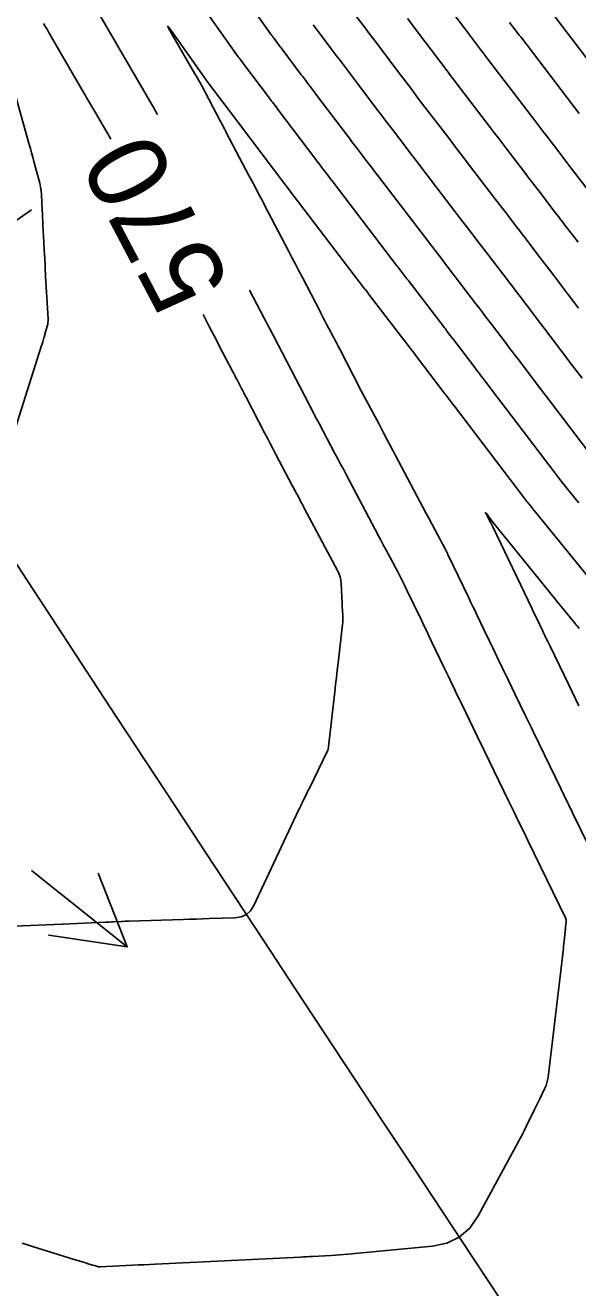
# Model space of a CAD drawing. Extents: x 954385 to 988206, y 1868364 to 1924553.
# Drawn here: x 957406.6 to 957448.5, y 1920437.4 to 1920532.9 of the extents above; entities that cross this region are included whole.
import ezdxf

# ---------------------------------------------------------------- set-up
doc = ezdxf.new("R2010")
doc.units = 0
for name, color, linetype in [('Default', 7, 'Continuous'), ('Ex_Contour Labels', 7, 'Continuous'), ('Ex_Major Contours', 7, 'Continuous'), ('Ex_Minor Contours', 7, 'Continuous'), ('Slopes', 7, 'Continuous')]:
    doc.layers.add(name, color=color, linetype=linetype)

msp = doc.modelspace()

# ---------------------------------------------------------------- linework, layer by layer
at = {"layer": 'Default'}
msp.add_arc((966995.782, 1926764.927), 11459.156, 211.4606918, 214.0750737, dxfattribs=at)
at = {"layer": 'Ex_Major Contours'}
for points in [[(957449.114, 1920500.826), (957446.06, 1920504.842), (957445.548, 1920505.515), (957445.037, 1920506.188), (957443.943, 1920507.626), (957443.722, 1920507.916), (957443.501, 1920508.207), (957443.281, 1920508.497), (957443.06, 1920508.787), (957441.933, 1920510.271), (957441.835, 1920510.4), (957441.737, 1920510.529), (957441.639, 1920510.658), (957441.541, 1920510.787), (957441.149, 1920511.303), (957441.051, 1920511.432), (957440.952, 1920511.561), (957440.854, 1920511.69), (957440.756, 1920511.818), (957438.698, 1920514.502), (957438.572, 1920514.667), (957438.445, 1920514.831), (957438.319, 1920514.996), (957438.193, 1920515.16), (957437.689, 1920515.818), (957437.562, 1920515.982), (957437.436, 1920516.147), (957437.31, 1920516.311), (957437.185, 1920516.476), (957433.308, 1920521.55), (957433.114, 1920521.803), (957432.92, 1920522.057), (957432.726, 1920522.311), (957432.532, 1920522.565), (957431.757, 1920523.58), (957431.563, 1920523.833), (957431.369, 1920524.087), (957431.176, 1920524.342), (957430.984, 1920524.596), (957428.799, 1920527.486), (957428.589, 1920527.763), (957428.38, 1920528.04), (957427.96, 1920528.595), (957427.856, 1920528.734), (957427.751, 1920528.872), (957427.646, 1920529.011), (957427.541, 1920529.15), (957426.004, 1920531.186), (957425.939, 1920531.273), (957425.873, 1920531.36), (957425.807, 1920531.447), (957425.741, 1920531.534), (957425.477, 1920531.883), (957425.411, 1920531.971), (957425.347, 1920532.059), (957425.282, 1920532.147), (957425.219, 1920532.236), (957421.065, 1920538.117)], [(957408.031, 1920533.031), (957408.178, 1920532.786), (957408.323, 1920532.541), (957408.467, 1920532.294), (957410.934, 1920528.044), (957411.16, 1920527.654), (957411.386, 1920527.264), (957411.613, 1920526.875), (957411.839, 1920526.485), (957412.987, 1920524.509), (957413.091, 1920524.327), (957413.119, 1920524.279)], [(957443.304, 1920533.114), (957443.722, 1920532.561), (957443.827, 1920532.422), (957443.932, 1920532.284), (957444.037, 1920532.146), (957444.142, 1920532.009), (957448.568, 1920526.218)], [(957420.103, 1920511.005), (957420.553, 1920510.142), (957420.749, 1920509.766), (957420.944, 1920509.391), (957421.14, 1920509.015), (957421.335, 1920508.64), (957422.338, 1920506.716), (957422.423, 1920506.552), (957422.509, 1920506.388), (957422.594, 1920506.224), (957422.68, 1920506.059), (957423.021, 1920505.403), (957423.107, 1920505.238), (957423.192, 1920505.074), (957423.278, 1920504.91), (957423.363, 1920504.745), (957424.755, 1920502.064), (957424.97, 1920501.653), (957425.185, 1920501.241), (957425.4, 1920500.831), (957425.617, 1920500.421), (957426.859, 1920498.075), (957426.95, 1920497.904), (957427.101, 1920497.618), (957427.162, 1920497.504), (957427.222, 1920497.39), (957427.507, 1920496.851), (957427.565, 1920496.742), (957427.623, 1920496.634), (957427.68, 1920496.525), (957427.738, 1920496.416), (957430.299, 1920491.587), (957430.398, 1920491.373), (957430.473, 1920491.152), (957430.522, 1920490.925), (957430.548, 1920490.691), (957430.606, 1920489.61), (957430.615, 1920489.437), (957430.624, 1920489.265), (957430.634, 1920489.093), (957430.643, 1920488.92), (957430.681, 1920488.231), (957430.687, 1920488.058), (957430.685, 1920487.886), (957430.676, 1920487.714), (957430.66, 1920487.543), (957430.32, 1920484.633), (957430.257, 1920484.09), (957430.194, 1920483.548), (957430.131, 1920483.006), (957430.068, 1920482.464), (957429.563, 1920478.105), (957429.558, 1920478.067), (957429.558, 1920478.062), (957429.556, 1920478.057), (957429.555, 1920478.053), (957429.553, 1920478.049), (957428.149, 1920475.175), (957428.083, 1920475.04), (957428.017, 1920474.906), (957427.951, 1920474.771), (957427.885, 1920474.636), (957427.622, 1920474.097), (957427.557, 1920473.962), (957427.492, 1920473.827), (957427.427, 1920473.692), (957427.363, 1920473.557), (957423.941, 1920466.29), (957423.696, 1920465.898), (957423.38, 1920465.613), (957422.993, 1920465.436), (957422.536, 1920465.365), (957420.565, 1920465.3), (957420.072, 1920465.283), (957419.58, 1920465.267), (957419.087, 1920465.251), (957418.594, 1920465.235), (957414.505, 1920465.102), (957414.355, 1920465.097), (957414.205, 1920465.092), (957414.055, 1920465.086), (957413.906, 1920465.079), (957413.307, 1920465.051), (957413.157, 1920465.044), (957413.007, 1920465.037), (957412.858, 1920465.031), (957412.708, 1920465.024), (957409.5, 1920464.876), (957409.439, 1920464.873), (957395.66, 1920464.306)]]:
    msp.add_lwpolyline(points, dxfattribs=at)
at = {"layer": 'Ex_Minor Contours'}
for points in [[(957448.551, 1920496.747), (957448.4, 1920496.933), (957448.249, 1920497.12), (957448.098, 1920497.306), (957447.947, 1920497.492), (957447.342, 1920498.237), (957447.192, 1920498.424), (957447.043, 1920498.612), (957446.896, 1920498.801), (957446.75, 1920498.992), (957442.633, 1920504.404), (957442.141, 1920505.052), (957441.32, 1920506.131), (957441.156, 1920506.347), (957440.992, 1920506.563), (957440.828, 1920506.779), (957440.663, 1920506.994), (957439.058, 1920509.107), (957438.935, 1920509.269), (957438.812, 1920509.432), (957438.566, 1920509.756), (957438.504, 1920509.837), (957438.442, 1920509.918), (957438.38, 1920509.999), (957438.318, 1920510.08), (957435.691, 1920513.506), (957435.615, 1920513.606), (957435.538, 1920513.706), (957435.462, 1920513.806), (957435.385, 1920513.906), (957435.078, 1920514.305), (957435.002, 1920514.405), (957434.925, 1920514.505), (957434.849, 1920514.605), (957434.772, 1920514.705), (957429.953, 1920521.012), (957429.843, 1920521.156), (957429.734, 1920521.3), (957429.624, 1920521.443), (957429.514, 1920521.587), (957429.076, 1920522.161), (957428.966, 1920522.304), (957428.857, 1920522.448), (957428.747, 1920522.592), (957428.638, 1920522.736), (957425.801, 1920526.489), (957425.632, 1920526.712), (957425.35, 1920527.085), (957425.294, 1920527.16), (957425.237, 1920527.234), (957425.181, 1920527.309), (957425.125, 1920527.383), (957423.172, 1920529.969), (957423.104, 1920530.06), (957423.036, 1920530.15), (957422.9, 1920530.33), (957422.866, 1920530.375), (957422.832, 1920530.421), (957422.799, 1920530.467), (957422.766, 1920530.513), (957417.792, 1920537.556)], [(957438.02, 1920535.141), (957439.887, 1920532.67), (957440.041, 1920532.467), (957440.194, 1920532.265), (957440.347, 1920532.062), (957440.5, 1920531.86), (957441.112, 1920531.05), (957441.266, 1920530.847), (957441.419, 1920530.645), (957441.573, 1920530.443), (957441.727, 1920530.241), (957445.212, 1920525.682), (957445.439, 1920525.385), (957445.666, 1920525.088), (957445.893, 1920524.791), (957446.12, 1920524.494), (957447.027, 1920523.307), (957447.254, 1920523.01), (957447.481, 1920522.713), (957447.708, 1920522.417), (957447.936, 1920522.12), (957449.844, 1920519.632)], [(957416.651, 1920526.138), (957416.609, 1920526.218), (957416.548, 1920526.329), (957416.486, 1920526.439), (957416.423, 1920526.549), (957412.117, 1920533.963)], [(957448.521, 1920511.494), (957448.373, 1920511.689), (957448.226, 1920511.883), (957447.635, 1920512.66), (957447.488, 1920512.854), (957447.34, 1920513.049), (957447.192, 1920513.243), (957447.045, 1920513.437), (957446.315, 1920514.397), (957446.144, 1920514.622), (957445.973, 1920514.847), (957445.801, 1920515.071), (957445.63, 1920515.295), (957444.688, 1920516.523), (957444.474, 1920516.803), (957444.26, 1920517.082), (957444.045, 1920517.361), (957443.831, 1920517.641), (957442.909, 1920518.843), (957442.684, 1920519.136), (957442.459, 1920519.43), (957442.234, 1920519.724), (957442.009, 1920520.018), (957440.018, 1920522.624), (957439.655, 1920523.098), (957439.293, 1920523.573), (957438.931, 1920524.047), (957438.568, 1920524.521), (957436.898, 1920526.706), (957436.646, 1920527.036), (957436.395, 1920527.366), (957436.144, 1920527.697), (957435.893, 1920528.028), (957434.795, 1920529.48), (957434.593, 1920529.747), (957434.391, 1920530.014), (957434.19, 1920530.281), (957433.988, 1920530.548), (957433.12, 1920531.696), (957432.949, 1920531.922), (957432.778, 1920532.149), (957432.607, 1920532.375), (957432.436, 1920532.602), (957431.669, 1920533.618)], [(957448.483, 1920516.49), (957448.319, 1920516.705), (957448.154, 1920516.919), (957447.496, 1920517.778), (957447.331, 1920517.993), (957447.167, 1920518.207), (957447.002, 1920518.422), (957446.838, 1920518.636), (957445.519, 1920520.355), (957445.244, 1920520.714), (957444.97, 1920521.072), (957444.696, 1920521.43), (957444.422, 1920521.789), (957443.102, 1920523.516), (957442.791, 1920523.923), (957442.48, 1920524.33), (957442.168, 1920524.738), (957441.857, 1920525.145), (957439.312, 1920528.474), (957439.109, 1920528.74), (957438.907, 1920529.006), (957438.705, 1920529.272), (957438.503, 1920529.539), (957437.696, 1920530.606), (957437.494, 1920530.873), (957437.293, 1920531.139), (957437.091, 1920531.406), (957436.889, 1920531.673), (957435.57, 1920533.418)], [(957459.028, 1920517.455), (957458.558, 1920518.072), (957458.543, 1920518.092), (957456.046, 1920521.378), (957456.014, 1920521.419), (957455.983, 1920521.46), (957455.873, 1920521.604), (957455.857, 1920521.624), (957452.619, 1920525.845), (957452.561, 1920525.92), (957452.503, 1920525.996), (957452.445, 1920526.072), (957452.387, 1920526.148), (957452.097, 1920526.528), (957451.981, 1920526.679), (957451.923, 1920526.755), (957446.556, 1920533.776)], [(957449.248, 1920491.148), (957445.296, 1920496.022), (957445.143, 1920496.21), (957444.99, 1920496.399), (957444.685, 1920496.775), (957444.609, 1920496.87), (957444.533, 1920496.965), (957444.459, 1920497.061), (957444.385, 1920497.157), (957439.206, 1920503.966), (957438.916, 1920504.347), (957438.627, 1920504.728), (957438.554, 1920504.823), (957438.482, 1920504.919), (957438.409, 1920505.014), (957438.337, 1920505.109), (957436.184, 1920507.943), (957436.083, 1920508.076), (957435.983, 1920508.209), (957435.957, 1920508.242), (957435.932, 1920508.275), (957435.907, 1920508.308), (957435.881, 1920508.341), (957432.685, 1920512.51), (957432.577, 1920512.651), (957432.468, 1920512.793), (957432.414, 1920512.864), (957432.36, 1920512.934), (957426.598, 1920520.475), (957426.496, 1920520.608), (957426.395, 1920520.742), (957426.369, 1920520.775), (957426.344, 1920520.808), (957426.319, 1920520.842), (957426.293, 1920520.875), (957422.795, 1920525.502), (957422.708, 1920525.617), (957420.34, 1920528.753), (957420.32, 1920528.78), (957420.313, 1920528.789), (957417.81, 1920532.334), (957417.537, 1920532.708), (957417.431, 1920532.822), (957417.491, 1920532.678), (957417.717, 1920532.275), (957419.49, 1920529.22), (957419.572, 1920529.078), (957419.654, 1920528.937), (957419.819, 1920528.654), (957419.86, 1920528.583), (957419.9, 1920528.511), (957419.939, 1920528.439), (957419.978, 1920528.367), (957421.405, 1920525.661), (957421.442, 1920525.592), (957421.478, 1920525.523), (957421.514, 1920525.454), (957421.55, 1920525.386), (957421.695, 1920525.11), (957421.731, 1920525.041), (957421.768, 1920524.973), (957421.804, 1920524.904), (957421.84, 1920524.835), (957423.605, 1920521.487), (957423.702, 1920521.303), (957423.799, 1920521.12), (957423.896, 1920520.937), (957423.993, 1920520.753), (957424.38, 1920520.02), (957424.477, 1920519.836), (957424.573, 1920519.653), (957424.67, 1920519.469), (957424.766, 1920519.285), (957426.567, 1920515.827), (957426.831, 1920515.321), (957427.095, 1920514.815), (957427.358, 1920514.308), (957427.622, 1920513.802), (957428.956, 1920511.242), (957429.08, 1920511.004), (957429.204, 1920510.765), (957429.329, 1920510.526), (957429.453, 1920510.287), (957429.95, 1920509.333), (957430.074, 1920509.094), (957430.198, 1920508.855), (957430.322, 1920508.616), (957430.446, 1920508.377), (957431.485, 1920506.378), (957431.681, 1920506), (957431.879, 1920505.622), (957432.077, 1920505.245), (957432.276, 1920504.868), (957433.424, 1920502.7), (957433.758, 1920502.068), (957433.854, 1920501.887), (957433.949, 1920501.707), (957434.345, 1920500.96), (957434.426, 1920500.806), (957434.508, 1920500.651), (957434.59, 1920500.497), (957434.672, 1920500.343), (957436.977, 1920495.995), (957437.211, 1920495.554), (957437.445, 1920495.113), (957438.047, 1920493.977), (957438.097, 1920493.883), (957438.147, 1920493.789), (957438.197, 1920493.695), (957438.247, 1920493.601), (957438.446, 1920493.224), (957438.496, 1920493.13), (957438.544, 1920493.035), (957438.592, 1920492.94), (957438.638, 1920492.844), (957440.192, 1920489.609), (957440.357, 1920489.265), (957440.523, 1920488.921), (957440.688, 1920488.577), (957440.853, 1920488.233), (957441.661, 1920486.55), (957441.753, 1920486.359), (957441.845, 1920486.169), (957441.936, 1920485.978), (957442.028, 1920485.787), (957442.496, 1920484.811), (957442.577, 1920484.641), (957442.659, 1920484.471), (957442.821, 1920484.131), (957442.862, 1920484.046), (957442.903, 1920483.961), (957442.944, 1920483.876), (957442.985, 1920483.792), (957443.709, 1920482.299), (957444.512, 1920480.643), (957444.661, 1920480.336), (957444.81, 1920480.03), (957444.959, 1920479.723), (957445.108, 1920479.416), (957446.782, 1920475.964), (957447.181, 1920475.142), (957447.238, 1920475.024), (957447.295, 1920474.907), (957447.352, 1920474.79), (957447.409, 1920474.672), (957447.792, 1920473.885), (957447.874, 1920473.714), (957447.957, 1920473.544), (957448.04, 1920473.374), (957448.123, 1920473.203), (957451.387, 1920466.489)], [(957448.792, 1920506.194), (957448.444, 1920506.651), (957448.097, 1920507.108), (957446.38, 1920509.366), (957446.195, 1920509.608), (957446.011, 1920509.85), (957445.827, 1920510.093), (957445.643, 1920510.335), (957444.807, 1920511.435), (957444.673, 1920511.612), (957444.538, 1920511.789), (957444.404, 1920511.966), (957444.27, 1920512.143), (957443.732, 1920512.85), (957443.597, 1920513.027), (957443.463, 1920513.204), (957443.328, 1920513.38), (957443.193, 1920513.557), (957441.704, 1920515.499), (957441.528, 1920515.728), (957441.353, 1920515.957), (957441.177, 1920516.186), (957441.001, 1920516.415), (957440.299, 1920517.33), (957440.123, 1920517.559), (957439.948, 1920517.789), (957439.772, 1920518.018), (957439.597, 1920518.247), (957436.663, 1920522.087), (957436.385, 1920522.451), (957436.107, 1920522.815), (957435.828, 1920523.179), (957435.55, 1920523.543), (957434.438, 1920524.998), (957434.16, 1920525.363), (957433.882, 1920525.727), (957433.605, 1920526.092), (957433.329, 1920526.457), (957431.797, 1920528.483), (957431.644, 1920528.686), (957431.49, 1920528.889), (957431.337, 1920529.091), (957431.184, 1920529.294), (957430.571, 1920530.105), (957430.418, 1920530.308), (957430.264, 1920530.51), (957430.111, 1920530.713), (957429.958, 1920530.916), (957428.837, 1920532.402), (957428.739, 1920532.531), (957428.641, 1920532.66), (957428.543, 1920532.79), (957428.446, 1920532.919)], [(957404.232, 1920497.233), (957407.888, 1920508.652), (957407.911, 1920508.724), (957407.933, 1920508.796), (957407.954, 1920508.869), (957407.975, 1920508.941), (957408.058, 1920509.232), (957408.079, 1920509.305), (957408.099, 1920509.378), (957408.12, 1920509.451), (957408.141, 1920509.523), (957408.315, 1920510.136), (957408.346, 1920510.263), (957408.366, 1920510.392), (957408.375, 1920510.521), (957408.373, 1920510.652), (957408.19, 1920513.916), (957408.178, 1920514.129), (957408.166, 1920514.342), (957408.155, 1920514.555), (957408.143, 1920514.768), (957408.095, 1920515.62), (957408.084, 1920515.833), (957408.072, 1920516.045), (957408.061, 1920516.258), (957408.05, 1920516.471), (957407.986, 1920517.767), (957407.971, 1920518.054), (957407.957, 1920518.341), (957407.943, 1920518.628), (957407.928, 1920518.915), (957407.87, 1920520.078), (957407.848, 1920520.367), (957407.809, 1920520.652), (957407.755, 1920520.936), (957407.686, 1920521.216), (957407.303, 1920522.593), (957407.213, 1920522.915), (957407.123, 1920523.237), (957407.034, 1920523.56), (957406.944, 1920523.882), (957405.362, 1920529.573)], [(957406.402, 1920440.741), (957406.805, 1920440.616), (957407.208, 1920440.49), (957410.348, 1920439.513), (957410.436, 1920439.486), (957410.525, 1920439.458), (957410.613, 1920439.43), (957410.702, 1920439.402), (957411.297, 1920439.214), (957411.319, 1920439.208), (957411.341, 1920439.201), (957411.749, 1920439.081), (957411.888, 1920439.04), (957412.12, 1920438.972), (957412.166, 1920438.96), (957412.213, 1920438.952), (957412.261, 1920438.949), (957412.309, 1920438.949), (957414.771, 1920439.07), (957415.198, 1920439.09), (957415.624, 1920439.111), (957416.05, 1920439.132), (957416.477, 1920439.153), (957427.483, 1920439.69), (957427.706, 1920439.701), (957427.929, 1920439.712), (957428.152, 1920439.723), (957428.375, 1920439.734), (957429.812, 1920439.806), (957430.125, 1920439.823), (957430.439, 1920439.844), (957430.752, 1920439.869), (957431.065, 1920439.897), (957437.46, 1920440.509), (957438.553, 1920440.736), (957439.495, 1920441.194), (957440.284, 1920441.881), (957440.921, 1920442.798), (957443.986, 1920448.441), (957444.134, 1920448.718), (957444.279, 1920448.996), (957444.421, 1920449.277), (957444.56, 1920449.559), (957445.19, 1920450.853), (957445.287, 1920451.054), (957445.385, 1920451.255), (957445.483, 1920451.455), (957445.58, 1920451.656), (957445.971, 1920452.458), (957446.06, 1920452.661), (957446.131, 1920452.869), (957446.184, 1920453.083), (957446.219, 1920453.302), (957447.353, 1920462.822), (957447.363, 1920462.913), (957447.374, 1920463.004), (957447.383, 1920463.095), (957447.393, 1920463.186), (957447.455, 1920463.806), (957447.46, 1920463.854), (957447.511, 1920464.334), (957447.519, 1920464.418), (957447.528, 1920464.502), (957447.537, 1920464.585), (957447.546, 1920464.669), (957447.583, 1920465.026), (957447.587, 1920465.112), (957447.578, 1920465.197), (957447.558, 1920465.279), (957447.525, 1920465.359), (957444.686, 1920471.203), (957444.321, 1920471.955), (957443.956, 1920472.707), (957443.591, 1920473.459), (957443.226, 1920474.212), (957441.405, 1920477.964), (957440.852, 1920479.104), (957439.678, 1920481.524), (957439.62, 1920481.644), (957439.562, 1920481.764), (957439.504, 1920481.884), (957439.446, 1920482.004), (957439.215, 1920482.485), (957439.1, 1920482.726), (957438.985, 1920482.966), (957438.651, 1920483.66), (957438.577, 1920483.816), (957438.502, 1920483.972), (957438.427, 1920484.127), (957438.352, 1920484.283), (957437.378, 1920486.31), (957437.191, 1920486.7), (957437.004, 1920487.09), (957436.816, 1920487.479), (957436.629, 1920487.869), (957435.538, 1920490.141), (957435.368, 1920490.49), (957435.195, 1920490.837), (957435.018, 1920491.182), (957434.838, 1920491.526), (957434.111, 1920492.898), (957433.929, 1920493.24), (957433.747, 1920493.583), (957433.565, 1920493.926), (957433.384, 1920494.269), (957430.933, 1920498.895), (957430.721, 1920499.295), (957430.509, 1920499.696), (957430.296, 1920500.097), (957430.084, 1920500.498), (957428.881, 1920502.772), (957428.811, 1920502.904), (957428.741, 1920503.036), (957428.601, 1920503.3), (957428.566, 1920503.366), (957428.531, 1920503.432), (957428.497, 1920503.499), (957428.462, 1920503.565), (957428.291, 1920503.895), (957428.251, 1920503.972), (957428.21, 1920504.05), (957428.17, 1920504.127), (957428.13, 1920504.204), (957426.081, 1920508.142), (957425.968, 1920508.359), (957425.855, 1920508.576), (957425.742, 1920508.793), (957425.629, 1920509.01), (957425.177, 1920509.877), (957425.064, 1920510.094), (957424.951, 1920510.311), (957424.838, 1920510.528), (957424.725, 1920510.745), (957423.625, 1920512.858)], [(957448.563, 1920487.258), (957448.413, 1920487.443), (957448.376, 1920487.489), (957448.338, 1920487.535), (957448.301, 1920487.581), (957448.263, 1920487.627), (957446.866, 1920489.345), (957446.788, 1920489.442), (957442.039, 1920495.299), (957442.024, 1920495.318), (957442.02, 1920495.322), (957441.547, 1920495.945), (957441.5, 1920496.003), (957441.48, 1920496.02), (957441.486, 1920495.995), (957441.519, 1920495.928), (957441.787, 1920495.422), (957441.821, 1920495.358), (957441.866, 1920495.272), (957441.878, 1920495.251), (957441.889, 1920495.229), (957441.9, 1920495.208), (957441.91, 1920495.186), (957442.024, 1920494.949), (957445.013, 1920488.726), (957445.1, 1920488.546), (957445.187, 1920488.365), (957445.274, 1920488.184), (957445.36, 1920488.004), (957445.789, 1920487.109), (957445.88, 1920486.919), (957445.972, 1920486.729), (957446.154, 1920486.349), (957446.2, 1920486.254), (957446.245, 1920486.159), (957446.291, 1920486.064), (957446.337, 1920485.969), (957447.781, 1920482.993), (957448.037, 1920482.465), (957448.293, 1920481.938), (957448.549, 1920481.41)]]:
    msp.add_lwpolyline(points, dxfattribs=at)
at = {"layer": 'Slopes'}
for points in [[(957407.131, 1920518.928), (957301.058, 1920445.099), (957303.609, 1920450.529), (957301.058, 1920445.099), (957307.036, 1920445.605)], [(957407.131, 1920468.928), (957414.363, 1920463.162), (957408.43, 1920464.056), (957414.363, 1920463.162), (957412.17, 1920468.747)]]:
    msp.add_lwpolyline(points, dxfattribs=at)

# ---------------------------------------------------------------- texts
at = {"layer": 'Ex_Contour Labels'}
msp.add_text('570', height=6, rotation=117.75198, dxfattribs=at).set_placement((957422.259, 1920513.35))

doc.saveas('drawing.dxf')
